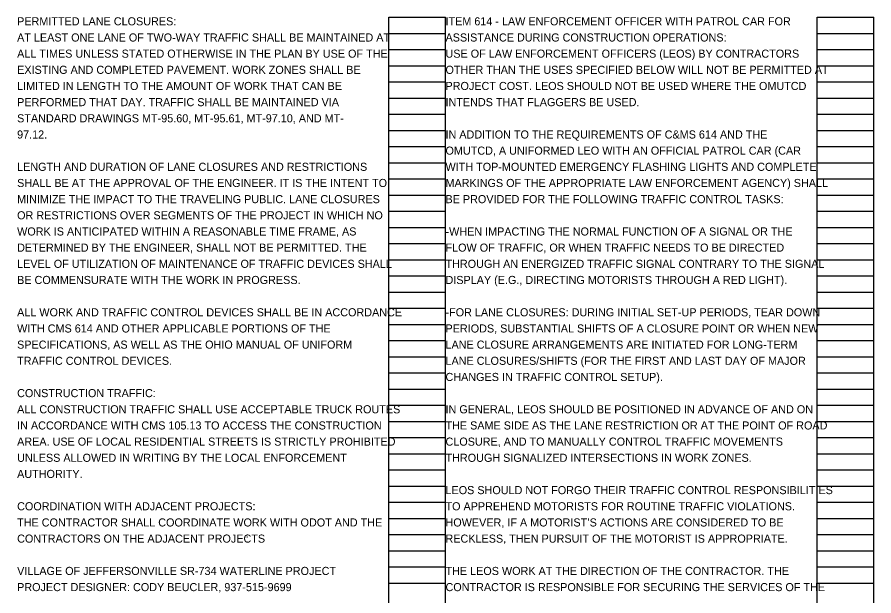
# Model space of a CAD drawing. Extents: x 37613.4 to 37668.4, y 18853.7 to 18946.8.
# Drawn here: x 37638.8 to 37653.64, y 18907.66 to 18917.68 of the extents above; entities that cross this region are included whole.
import ezdxf

# ---------------------------------------------------------------- set-up
doc = ezdxf.new("R2010")
doc.units = 0
doc.layers.add('SH_Data', color=7, linetype='Continuous')
doc.layers.add('SH_Text', color=7, linetype='Continuous')

msp = doc.modelspace()

# ---------------------------------------------------------------- linework, layer by layer
at = {"layer": 'SH_Data'}
for p, q in [((37645.241, 18897.522), (37645.241, 18917.682)), ((37645.241, 18917.682), (37646.221, 18917.682)), ((37646.221, 18897.522), (37646.221, 18917.682)), ((37652.661, 18897.522), (37652.661, 18917.682)), ((37652.661, 18917.682), (37653.641, 18917.682)), ((37653.641, 18897.522), (37653.641, 18917.682)), ((37645.241, 18917.402), (37646.221, 18917.402)), ((37652.661, 18917.402), (37653.641, 18917.402)), ((37645.241, 18917.122), (37646.221, 18917.122)), ((37652.661, 18917.122), (37653.641, 18917.122)), ((37645.241, 18916.842), (37646.221, 18916.842)), ((37652.661, 18916.842), (37653.641, 18916.842)), ((37645.241, 18916.562), (37646.221, 18916.562)), ((37652.661, 18916.562), (37653.641, 18916.562)), ((37645.241, 18916.282), (37646.221, 18916.282)), ((37652.661, 18916.282), (37653.641, 18916.282)), ((37645.241, 18916.002), (37646.221, 18916.002)), ((37652.661, 18916.002), (37653.641, 18916.002)), ((37645.241, 18915.722), (37646.221, 18915.722)), ((37652.661, 18915.722), (37653.641, 18915.722)), ((37645.241, 18915.442), (37646.221, 18915.442)), ((37652.661, 18915.442), (37653.641, 18915.442)), ((37645.241, 18915.162), (37646.221, 18915.162)), ((37652.661, 18915.162), (37653.641, 18915.162)), ((37645.241, 18914.882), (37646.221, 18914.882)), ((37652.661, 18914.882), (37653.641, 18914.882)), ((37645.241, 18914.602), (37646.221, 18914.602)), ((37652.661, 18914.602), (37653.641, 18914.602)), ((37645.241, 18914.322), (37646.221, 18914.322)), ((37652.661, 18914.322), (37653.641, 18914.322)), ((37645.241, 18914.042), (37646.221, 18914.042)), ((37652.661, 18914.042), (37653.641, 18914.042)), ((37645.241, 18913.762), (37646.221, 18913.762)), ((37652.661, 18913.762), (37653.641, 18913.762)), ((37645.241, 18913.482), (37646.221, 18913.482)), ((37652.661, 18913.482), (37653.641, 18913.482)), ((37645.241, 18913.202), (37646.221, 18913.202)), ((37652.661, 18913.202), (37653.641, 18913.202)), ((37645.241, 18912.922), (37646.221, 18912.922)), ((37652.661, 18912.922), (37653.641, 18912.922)), ((37645.241, 18912.642), (37646.221, 18912.642)), ((37652.661, 18912.642), (37653.641, 18912.642)), ((37645.241, 18912.362), (37646.221, 18912.362)), ((37652.661, 18912.362), (37653.641, 18912.362)), ((37645.241, 18912.082), (37646.221, 18912.082)), ((37652.661, 18912.082), (37653.641, 18912.082)), ((37645.241, 18911.802), (37646.221, 18911.802)), ((37652.661, 18911.802), (37653.641, 18911.802)), ((37645.241, 18911.522), (37646.221, 18911.522)), ((37652.661, 18911.522), (37653.641, 18911.522)), ((37645.241, 18911.242), (37646.221, 18911.242)), ((37652.661, 18911.242), (37653.641, 18911.242)), ((37645.241, 18910.962), (37646.221, 18910.962)), ((37652.661, 18910.962), (37653.641, 18910.962)), ((37645.241, 18910.682), (37646.221, 18910.682)), ((37652.661, 18910.682), (37653.641, 18910.682)), ((37645.241, 18910.402), (37646.221, 18910.402)), ((37652.661, 18910.402), (37653.641, 18910.402)), ((37645.241, 18910.122), (37646.221, 18910.122)), ((37652.661, 18910.122), (37653.641, 18910.122)), ((37645.241, 18909.842), (37646.221, 18909.842)), ((37652.661, 18909.842), (37653.641, 18909.842)), ((37645.241, 18909.562), (37646.221, 18909.562)), ((37652.661, 18909.562), (37653.641, 18909.562)), ((37645.241, 18909.282), (37646.221, 18909.282)), ((37652.661, 18909.282), (37653.641, 18909.282)), ((37645.241, 18909.002), (37646.221, 18909.002)), ((37652.661, 18909.002), (37653.641, 18909.002)), ((37645.241, 18908.722), (37646.221, 18908.722)), ((37652.661, 18908.722), (37653.641, 18908.722)), ((37645.241, 18908.442), (37646.221, 18908.442)), ((37652.661, 18908.442), (37653.641, 18908.442)), ((37645.241, 18908.162), (37646.221, 18908.162)), ((37652.661, 18908.162), (37653.641, 18908.162)), ((37645.241, 18907.882), (37646.221, 18907.882)), ((37652.661, 18907.882), (37653.641, 18907.882))]:
    msp.add_line(p, q, dxfattribs=at)

# ---------------------------------------------------------------- texts
at = {"layer": 'SH_Text'}
for s, p in [('PERMITTED LANE CLOSURES:', (37638.801, 18917.542)), ('ITEM 614 - LAW ENFORCEMENT OFFICER WITH PATROL CAR FOR ', (37646.221, 18917.542)), ('AT LEAST ONE LANE OF TWO-WAY TRAFFIC SHALL BE MAINTAINED AT ', (37638.801, 18917.262)), ('ASSISTANCE DURING CONSTRUCTION OPERATIONS:', (37646.221, 18917.262)), ('ALL TIMES UNLESS STATED OTHERWISE IN THE PLAN BY USE OF THE ', (37638.801, 18916.982)), ('USE OF LAW ENFORCEMENT OFFICERS (LEOS) BY CONTRACTORS ', (37646.221, 18916.982)), ('EXISTING AND COMPLETED PAVEMENT. WORK ZONES SHALL BE ', (37638.801, 18916.702)), ('OTHER THAN THE USES SPECIFIED BELOW WILL NOT BE PERMITTED AT ', (37646.221, 18916.702)), ('LIMITED IN LENGTH TO THE AMOUNT OF WORK THAT CAN BE ', (37638.801, 18916.422)), ('PROJECT COST. LEOS SHOULD NOT BE USED WHERE THE OMUTCD ', (37646.221, 18916.422)), ('PERFORMED THAT DAY. TRAFFIC SHALL BE MAINTAINED VIA ', (37638.801, 18916.142)), ('INTENDS THAT FLAGGERS BE USED.', (37646.221, 18916.142)), ('STANDARD DRAWINGS MT-95.60, MT-95.61, MT-97.10, AND MT-', (37638.801, 18915.862)), ('97.12. ', (37638.801, 18915.582)), ('IN ADDITION TO THE REQUIREMENTS OF C&MS 614 AND THE ', (37646.221, 18915.582)), ('OMUTCD, A UNIFORMED LEO WITH AN OFFICIAL PATROL CAR (CAR ', (37646.221, 18915.302)), ('LENGTH AND DURATION OF LANE CLOSURES AND RESTRICTIONS ', (37638.801, 18915.022)), ('WITH TOP-MOUNTED EMERGENCY FLASHING LIGHTS AND COMPLETE ', (37646.221, 18915.022)), ('SHALL BE AT THE APPROVAL OF THE ENGINEER. IT IS THE INTENT TO ', (37638.801, 18914.742)), ('MARKINGS OF THE APPROPRIATE LAW ENFORCEMENT AGENCY) SHALL ', (37646.221, 18914.742)), ('MINIMIZE THE IMPACT TO THE TRAVELING PUBLIC. LANE CLOSURES ', (37638.801, 18914.462)), ('BE PROVIDED FOR THE FOLLOWING TRAFFIC CONTROL TASKS:', (37646.221, 18914.462)), ('OR RESTRICTIONS OVER SEGMENTS OF THE PROJECT IN WHICH NO ', (37638.801, 18914.182)), ('WORK IS ANTICIPATED WITHIN A REASONABLE TIME FRAME, AS ', (37638.801, 18913.902)), ('-WHEN IMPACTING THE NORMAL FUNCTION OF A SIGNAL OR THE ', (37646.221, 18913.902)), ('DETERMINED BY THE ENGINEER, SHALL NOT BE PERMITTED. THE ', (37638.801, 18913.622)), ('FLOW OF TRAFFIC, OR WHEN TRAFFIC NEEDS TO BE DIRECTED ', (37646.221, 18913.622)), ('LEVEL OF UTILIZATION OF MAINTENANCE OF TRAFFIC DEVICES SHALL ', (37638.801, 18913.342)), ('THROUGH AN ENERGIZED TRAFFIC SIGNAL CONTRARY TO THE SIGNAL ', (37646.221, 18913.342)), ('BE COMMENSURATE WITH THE WORK IN PROGRESS.', (37638.801, 18913.062)), ('DISPLAY (E.G., DIRECTING MOTORISTS THROUGH A RED LIGHT). ', (37646.221, 18913.062)), ('ALL WORK AND TRAFFIC CONTROL DEVICES SHALL BE IN ACCORDANCE ', (37638.801, 18912.502)), ('-FOR LANE CLOSURES: DURING INITIAL SET-UP PERIODS, TEAR DOWN ', (37646.221, 18912.502)), ('WITH CMS 614 AND OTHER APPLICABLE PORTIONS OF THE ', (37638.801, 18912.222)), ('PERIODS, SUBSTANTIAL SHIFTS OF A CLOSURE POINT OR WHEN NEW ', (37646.221, 18912.222)), ('SPECIFICATIONS, AS WELL AS THE OHIO MANUAL OF UNIFORM ', (37638.801, 18911.942)), ('LANE CLOSURE ARRANGEMENTS ARE INITIATED FOR LONG-TERM ', (37646.221, 18911.942)), ('TRAFFIC CONTROL DEVICES.', (37638.801, 18911.662)), ('LANE CLOSURES/SHIFTS (FOR THE FIRST AND LAST DAY OF MAJOR ', (37646.221, 18911.662)), ('CHANGES IN TRAFFIC CONTROL SETUP).', (37646.221, 18911.382)), ('CONSTRUCTION TRAFFIC:', (37638.801, 18911.102)), ('ALL CONSTRUCTION TRAFFIC SHALL USE ACCEPTABLE TRUCK ROUTES ', (37638.801, 18910.822)), ('IN GENERAL, LEOS SHOULD BE POSITIONED IN ADVANCE OF AND ON ', (37646.221, 18910.822)), ('IN ACCORDANCE WITH CMS 105.13 TO ACCESS THE CONSTRUCTION ', (37638.801, 18910.542)), ('THE SAME SIDE AS THE LANE RESTRICTION OR AT THE POINT OF ROAD ', (37646.221, 18910.542)), ('AREA. USE OF LOCAL RESIDENTIAL STREETS IS STRICTLY PROHIBITED ', (37638.801, 18910.262)), ('CLOSURE, AND TO MANUALLY CONTROL TRAFFIC MOVEMENTS ', (37646.221, 18910.262)), ('UNLESS ALLOWED IN WRITING BY THE LOCAL ENFORCEMENT ', (37638.801, 18909.982)), ('THROUGH SIGNALIZED INTERSECTIONS IN WORK ZONES. ', (37646.221, 18909.982)), ('AUTHORITY.', (37638.801, 18909.702)), ('LEOS SHOULD NOT FORGO THEIR TRAFFIC CONTROL RESPONSIBILITIES ', (37646.221, 18909.422)), ('COORDINATION WITH ADJACENT PROJECTS:', (37638.801, 18909.142)), ('TO APPREHEND MOTORISTS FOR ROUTINE TRAFFIC VIOLATIONS. ', (37646.221, 18909.142)), ('THE CONTRACTOR SHALL COORDINATE WORK WITH ODOT AND THE ', (37638.801, 18908.862)), ('HOWEVER, IF A MOTORIST’S ACTIONS ARE CONSIDERED TO BE ', (37646.221, 18908.862)), ('CONTRACTORS ON THE ADJACENT PROJECTS', (37638.801, 18908.582)), (': ', (37642.762, 18908.582)), ('RECKLESS, THEN PURSUIT OF THE MOTORIST IS APPROPRIATE. ', (37646.221, 18908.582)), ('VILLAGE OF JEFFERSONVILLE SR-734 WATERLINE PROJECT', (37638.801, 18908.022)), ('THE LEOS WORK AT THE DIRECTION OF THE CONTRACTOR. THE ', (37646.221, 18908.022)), ('PROJECT DESIGNER: CODY BEUCLER, 937-515-9699', (37638.801, 18907.742)), ('CONTRACTOR IS RESPONSIBLE FOR SECURING THE SERVICES OF THE ', (37646.221, 18907.742))]:
    msp.add_text(s, height=0.14, dxfattribs=at).set_placement(p)

doc.saveas('drawing.dxf')
